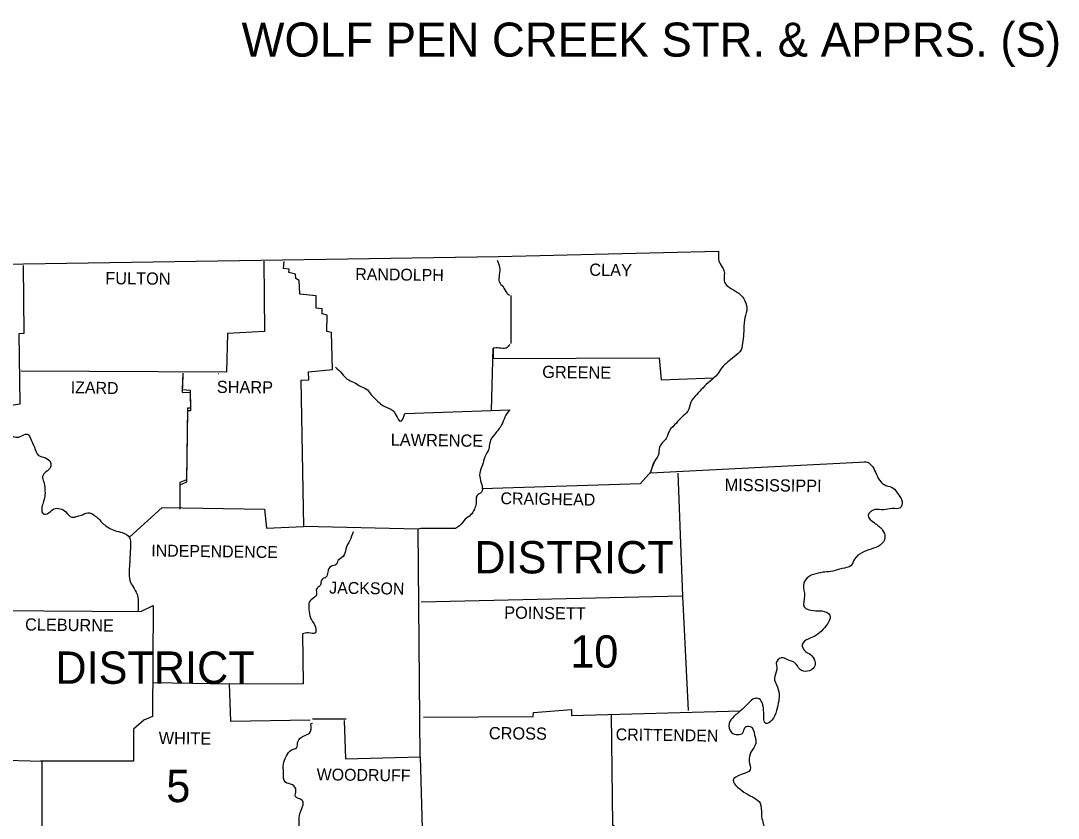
# Model space of a CAD drawing. Extents: x 1373884 to 1377798, y 1168424 to 1170626.
# Drawn here: x 1376598.2 to 1376963.9, y 1170086.2 to 1170367.2 of the extents above; entities that cross this region are included whole.
import ezdxf

# ---------------------------------------------------------------- set-up
doc = ezdxf.new("R2010")
doc.units = 0
doc.layers.add('1', color=7, linetype='Continuous')
doc.layers.add('R_Draft', color=7, linetype='Continuous')

msp = doc.modelspace()

# ---------------------------------------------------------------- linework, layer by layer
at = {"layer": 'R_Draft'}
for p, q in [((1376770.39, 1170230), (1376770.69, 1170230.1)), ((1376820.19, 1170207.9), (1376821.39, 1170211.6)), ((1376820.49, 1170209.1), (1376821.69, 1170212)), ((1376700.99, 1170121.3), (1376712.89, 1170121.3))]:
    msp.add_line(p, q, dxfattribs=at)
for points in [[(1376295.59, 1170281.4), (1376457.29, 1170281.3), (1376599.19, 1170281.6), (1376766.59, 1170284.2), (1376844.19, 1170286)], [(1376683.89, 1170282.5), (1376684.09, 1170257.7), (1376671.09, 1170257), (1376670.69, 1170243.4), (1376598.39, 1170243.8)], [(1376712.19, 1170120.7), (1376712.69, 1170107.2), (1376738.99, 1170107.9), (1376738.29, 1170188.1), (1376697.99, 1170189), (1376697.09, 1170240.6), (1376699.69, 1170240.7), (1376699.59, 1170243.5), (1376708.09, 1170244.3), (1376707.69, 1170257.4), (1376706.09, 1170257.7), (1376706.19, 1170263.5), (1376704.39, 1170264), (1376704.39, 1170265.7), (1376702.29, 1170266), (1376702.29, 1170270.3), (1376696.59, 1170270.9), (1376696.29, 1170275.7), (1376695.19, 1170276.4), (1376694.99, 1170278), (1376692.69, 1170278.5), (1376692.79, 1170279.7), (1376690.79, 1170280), (1376691.09, 1170282.4)], [(1376568.89, 1170039.7), (1376591.39, 1170039.8), (1376592.39, 1170051.6), (1376605.79, 1170052.6), (1376605.79, 1170106.2), (1376588.79, 1170106.7), (1376589.09, 1170159.4), (1376567.69, 1170160.8), (1376567.39, 1170184.4), (1376566.69, 1170185.6), (1376567.29, 1170200.4), (1376579.69, 1170200.8), (1376580.19, 1170213), (1376593.79, 1170213.5), (1376593.99, 1170221.4), (1376591.59, 1170224.5), (1376590.99, 1170231.2), (1376597.99, 1170232.2), (1376597.69, 1170257.1), (1376599.39, 1170257.2), (1376599.19, 1170281)], [(1376770.99, 1170270.4), (1376770.99, 1170253.5)], [(1376764.17, 1170229.87), (1376764.69, 1170251.9), (1376764.69, 1170248.2), (1376823.19, 1170248.5), (1376823.99, 1170240.7), (1376842.35, 1170241.37)], [(1376655.29, 1170243.1), (1376655.09, 1170237.3), (1376657.89, 1170237.1), (1376657.99, 1170230.7), (1376656.99, 1170230.7), (1376656.59, 1170205.5), (1376654.29, 1170204.5), (1376654.29, 1170196.1)], [(1376655.29, 1170242.2), (1376655.09, 1170236.4), (1376657.89, 1170236.2), (1376657.99, 1170229.8), (1376656.99, 1170229.8), (1376656.59, 1170204.6), (1376654.29, 1170203.6), (1376654.29, 1170195.2)], [(1376667.79, 1170242.9), (1376667.89, 1170243)], [(1376733.59, 1170228.8), (1376770.69, 1170230.1)], [(1376820.19, 1170207.9), (1376896.09, 1170211.8)], [(1376760.69, 1170202.39), (1376816.69, 1170204.2), (1376820.36, 1170208.43)], [(1376829.79, 1170207.8), (1376831.49, 1170164.5), (1376833.49, 1170124.2)], [(1376636.69, 1170185.4), (1376648.09, 1170195.7), (1376684.09, 1170195.2), (1376684.79, 1170188.5), (1376697.89, 1170189)], [(1376751.39, 1170188.3), (1376739.19, 1170188.3), (1376738.29, 1170188.1)], [(1376831.49, 1170164.5), (1376739.39, 1170162.4)], [(1376589.09, 1170159.4), (1376640.49, 1170159.1), (1376644.89, 1170161.2), (1376644.59, 1170122.1), (1376641.59, 1170120.8), (1376638.89, 1170118.5), (1376637.99, 1170117.6), (1376637.89, 1170106.4), (1376605.19, 1170106.4)], [(1376697.49, 1170151.2), (1376697.69, 1170133.6), (1376671.69, 1170133.5), (1376644.99, 1170134)], [(1376671.69, 1170133.5), (1376672.09, 1170120.4), (1376700.19, 1170120.9)], [(1376740.19, 1170121.9), (1376778.79, 1170122.1), (1376778.89, 1170123.5), (1376792.29, 1170124.5), (1376792.29, 1170122.4), (1376851.86, 1170124.04)], [(1376806.29, 1170122.79), (1376806.79, 1170083.9), (1376807.69, 1170083.3), (1376808.01, 1170077.77)], [(1376700.99, 1170119.6), (1376700.49, 1170119.5)], [(1376738.99, 1170107.9), (1376740.49, 1170053.1), (1376716.69, 1170053), (1376716.59, 1170050.8), (1376709.69, 1170050.4), (1376709.09, 1170039), (1376700.69, 1170039)]]:
    msp.add_lwpolyline(points, dxfattribs=at)
for points in [[(1376844.19, 1170286), (1376844.69, 1170281.6), (1376846.09, 1170279.3), (1376846.29, 1170275.1), (1376847.99, 1170273.3), (1376850.89, 1170271.5), (1376853.49, 1170268.6), (1376854.09, 1170265.2), (1376853.29, 1170261.7), (1376853.09, 1170257.8), (1376852.69, 1170254.4), (1376852.09, 1170251.3), (1376849.69, 1170248.8), (1376847.39, 1170247), (1376845.29, 1170244.9), (1376843.79, 1170242.7), (1376841.19, 1170240.3), (1376838.59, 1170237.8), (1376836.49, 1170235.6), (1376834.39, 1170232.8), (1376833.39, 1170229.7), (1376831.09, 1170227.5), (1376829.29, 1170225.5), (1376826.89, 1170222.8), (1376825.69, 1170220.1), (1376823.39, 1170217), (1376822.89, 1170214), (1376821.39, 1170211.6), (1376821.29, 1170211.2)], [(1376844.19, 1170286), (1376844.69, 1170281.6), (1376846.09, 1170279.3), (1376846.29, 1170275.1), (1376847.99, 1170273.3), (1376850.89, 1170271.5), (1376853.49, 1170268.6), (1376854.09, 1170265.2), (1376853.29, 1170261.7), (1376853.09, 1170257.8), (1376852.69, 1170254.4), (1376852.09, 1170251.3), (1376849.69, 1170248.8), (1376847.39, 1170247), (1376845.29, 1170244.9), (1376843.79, 1170242.7), (1376841.19, 1170240.3), (1376838.59, 1170237.8), (1376836.49, 1170235.6), (1376834.39, 1170232.8), (1376833.39, 1170229.7), (1376831.09, 1170227.5), (1376829.29, 1170225.5), (1376826.89, 1170222.8), (1376825.69, 1170220.1), (1376823.39, 1170217), (1376822.89, 1170214), (1376821.39, 1170211.6), (1376821.29, 1170211.2)], [(1376766.09, 1170282.9), (1376766.99, 1170280.4), (1376766.89, 1170277.7), (1376766.89, 1170275.2), (1376768.19, 1170273.5), (1376769.49, 1170271.4), (1376770.49, 1170270.5)], [(1376770.59, 1170253.2), (1376769.29, 1170251.9), (1376766.79, 1170251.9), (1376764.69, 1170251.9)], [(1376709.19, 1170245.2), (1376711.39, 1170242.9), (1376713.29, 1170241), (1376715.49, 1170239.9), (1376718.09, 1170238.4), (1376720.39, 1170237.2), (1376721.89, 1170235.3), (1376723.99, 1170233.2), (1376726.09, 1170231.5), (1376729.39, 1170229.9), (1376730.49, 1170228.2), (1376731.99, 1170226.1), (1376733.59, 1170228.8)], [(1376770.39, 1170230), (1376768.89, 1170227.6), (1376767.69, 1170224.8), (1376765.29, 1170221.6), (1376763.49, 1170218.5), (1376763.19, 1170216.4), (1376761.79, 1170213.6), (1376760.99, 1170210.8), (1376760.09, 1170208.4), (1376760.09, 1170205.9), (1376760.79, 1170203.4), (1376760.59, 1170201.1), (1376759.09, 1170200), (1376758.69, 1170197.1), (1376758.09, 1170195.1), (1376756.79, 1170193.1), (1376754.89, 1170191.6), (1376752.89, 1170189.3), (1376751.39, 1170188.3)], [(1376593.99, 1170221.4), (1376597.99, 1170220.7), (1376600.39, 1170221.6), (1376602.09, 1170219), (1376602.99, 1170217), (1376604.49, 1170214.1), (1376606.89, 1170213.2), (1376608.69, 1170211.6), (1376608.69, 1170209.9), (1376607.09, 1170208.3), (1376605.89, 1170206.7), (1376606.29, 1170204.8), (1376606.69, 1170202.2), (1376606.69, 1170199.7), (1376606.09, 1170197.4), (1376605.59, 1170195.3), (1376606.09, 1170193.5), (1376607.99, 1170193.8), (1376609.99, 1170195.3), (1376612.09, 1170195.3), (1376614.09, 1170194.2), (1376616.19, 1170192.3), (1376618.29, 1170192.7), (1376619.99, 1170193.2), (1376622.39, 1170193.9), (1376624.09, 1170193), (1376625.59, 1170191.8), (1376627.39, 1170189.9), (1376629.09, 1170188.7), (1376631.29, 1170187.6), (1376633.99, 1170186.9), (1376636.49, 1170185.2), (1376636.89, 1170182.3), (1376636.79, 1170179.8), (1376636.59, 1170176.7), (1376636.39, 1170173.3), (1376636.69, 1170170), (1376637.79, 1170167.8), (1376639.19, 1170165.2), (1376639.59, 1170162.8), (1376639.49, 1170159)], [(1376894.99, 1170211.7), (1376896.09, 1170211.8), (1376899.49, 1170208.2), (1376900.99, 1170205.2), (1376903.19, 1170203.5), (1376905.69, 1170202.6), (1376907.59, 1170200.3), (1376908.89, 1170197.8), (1376908.19, 1170195.6), (1376905.39, 1170195.4), (1376902.29, 1170194.9), (1376899.29, 1170195), (1376896.89, 1170193), (1376899.09, 1170190.3), (1376901.99, 1170187.8), (1376902.79, 1170185.1), (1376901.19, 1170182.5), (1376897.99, 1170181.1), (1376894.89, 1170179.9), (1376892.09, 1170177.5), (1376890.79, 1170175.2), (1376887.69, 1170174.2), (1376884.49, 1170173.3), (1376881.69, 1170173), (1376878.49, 1170172.4), (1376875.39, 1170170.9), (1376874.09, 1170168.3), (1376874.49, 1170164.6), (1376874.39, 1170160.7), (1376877.69, 1170159.4), (1376880.59, 1170159.3), (1376883.39, 1170157.8), (1376883.09, 1170155.6), (1376880.99, 1170152.8), (1376878.49, 1170150.6), (1376875.99, 1170149.5), (1376873.69, 1170147.4), (1376874.49, 1170145.3), (1376876.59, 1170143.9), (1376878.09, 1170141.6), (1376877.89, 1170139.5), (1376875.49, 1170138), (1376872.89, 1170138.6), (1376870.99, 1170141.1), (1376868.79, 1170141.9), (1376866.89, 1170142.8), (1376864.69, 1170141.5), (1376864.69, 1170138.6), (1376863.89, 1170135.5), (1376864.59, 1170133.2), (1376865.49, 1170130), (1376865.39, 1170127.6), (1376864.59, 1170124.2), (1376862.89, 1170120.7), (1376860.89, 1170119.6), (1376860.09, 1170123.4), (1376859.69, 1170126.5), (1376858.49, 1170128.3), (1376856.89, 1170128.4), (1376854.79, 1170126.9), (1376852.49, 1170124.6), (1376849.59, 1170122.1), (1376847.89, 1170119.6), (1376848.79, 1170116.5), (1376850.99, 1170115.7), (1376852.69, 1170116.3), (1376853.59, 1170118.3), (1376855.29, 1170118.6), (1376856.89, 1170115.5)], [(1376894.99, 1170211.7), (1376896.09, 1170211.8), (1376899.49, 1170208.2), (1376900.99, 1170205.2), (1376903.19, 1170203.5), (1376905.69, 1170202.6), (1376907.59, 1170200.3), (1376908.89, 1170197.8), (1376908.19, 1170195.6), (1376905.39, 1170195.4), (1376902.29, 1170194.9), (1376899.29, 1170195), (1376896.89, 1170193), (1376899.09, 1170190.3), (1376901.99, 1170187.8), (1376902.79, 1170185.1), (1376901.19, 1170182.5), (1376897.99, 1170181.1), (1376894.89, 1170179.9), (1376892.09, 1170177.5), (1376890.79, 1170175.2), (1376887.69, 1170174.2), (1376884.49, 1170173.3), (1376881.69, 1170173), (1376878.49, 1170172.4), (1376875.39, 1170170.9), (1376874.09, 1170168.3), (1376874.49, 1170164.6), (1376874.39, 1170160.7), (1376877.69, 1170159.4), (1376880.59, 1170159.3), (1376883.39, 1170157.8), (1376883.09, 1170155.6), (1376880.99, 1170152.8), (1376878.49, 1170150.6), (1376875.99, 1170149.5), (1376873.69, 1170147.4), (1376874.49, 1170145.3), (1376876.59, 1170143.9), (1376878.09, 1170141.6), (1376877.89, 1170139.5), (1376875.49, 1170138), (1376872.89, 1170138.6), (1376870.99, 1170141.1), (1376868.79, 1170141.9), (1376866.89, 1170142.8), (1376864.69, 1170141.5), (1376864.69, 1170138.6), (1376863.89, 1170135.5), (1376864.59, 1170133.2), (1376865.49, 1170130), (1376865.39, 1170127.6), (1376864.59, 1170124.2), (1376862.89, 1170120.7), (1376860.89, 1170119.6), (1376860.09, 1170123.4), (1376859.69, 1170126.5), (1376858.49, 1170128.3), (1376856.89, 1170128.4), (1376854.79, 1170126.9), (1376852.49, 1170124.6), (1376849.59, 1170122.1), (1376847.89, 1170119.6), (1376848.79, 1170116.5), (1376850.99, 1170115.7), (1376852.69, 1170116.3), (1376853.59, 1170118.3), (1376855.29, 1170118.6), (1376856.89, 1170115.5)], [(1376715.39, 1170187.2), (1376714.19, 1170184.1), (1376712.79, 1170181.1), (1376711.89, 1170178.5), (1376709.99, 1170177), (1376709.39, 1170175.6), (1376707.69, 1170175), (1376706.39, 1170173), (1376705.79, 1170171.2), (1376704.39, 1170170.4), (1376703.69, 1170168.2), (1376702.39, 1170167), (1376702.49, 1170165), (1376700.99, 1170163.6), (1376699.79, 1170162), (1376699.79, 1170159.8), (1376700.29, 1170156.9), (1376701.29, 1170155.2), (1376702.19, 1170153), (1376702.09, 1170151.6), (1376699.59, 1170151.6), (1376697.49, 1170151.2)], [(1376688.29, 1170059.8), (1376687.79, 1170060.5), (1376688.39, 1170062.7), (1376688.69, 1170064.1), (1376687.69, 1170066.1), (1376688.59, 1170067.8), (1376689.59, 1170069.6), (1376689.89, 1170071.7), (1376690.69, 1170073.1), (1376690.39, 1170074.9), (1376690.79, 1170077.4), (1376691.89, 1170079.3), (1376693.49, 1170082), (1376696.19, 1170082.7), (1376696.39, 1170083.8), (1376696.29, 1170086.3), (1376697.39, 1170090), (1376697.79, 1170091.3), (1376697.39, 1170092.5), (1376694.99, 1170093.9), (1376695.19, 1170096), (1376693.99, 1170098), (1376691.49, 1170098.9), (1376690.79, 1170102.3), (1376690.79, 1170105.3), (1376691.89, 1170108.2), (1376693.59, 1170110.3), (1376695.39, 1170111.1), (1376695.89, 1170113.1), (1376698.09, 1170115.3), (1376699.99, 1170116.2), (1376700.49, 1170119.5)], [(1376856.89, 1170115.5), (1376857.29, 1170112.6), (1376855.59, 1170109.5), (1376854.99, 1170106.4), (1376855.29, 1170103.3), (1376852.09, 1170101.6), (1376849.29, 1170099.6), (1376850.89, 1170097.2), (1376853.89, 1170095), (1376856.89, 1170093.3), (1376858.79, 1170091.6), (1376859.29, 1170087.5), (1376859.79, 1170084.9), (1376860.79, 1170081.3), (1376861.19, 1170078.8), (1376859.39, 1170075.8), (1376857.29, 1170075.2), (1376855.09, 1170075.9), (1376852.49, 1170076.1), (1376850.39, 1170074.1), (1376848.89, 1170071.3), (1376847.39, 1170068.5), (1376846.29, 1170066.1), (1376845.19, 1170063.5), (1376842.99, 1170060.5), (1376840.29, 1170060), (1376837.09, 1170059.2), (1376835.19, 1170057), (1376835.49, 1170053.3), (1376837.29, 1170050.8), (1376838.69, 1170047.7), (1376839.69, 1170045), (1376839.19, 1170041.6), (1376837.79, 1170039.1), (1376835.99, 1170037.6), (1376835.19, 1170034.4), (1376833.89, 1170032), (1376832.69, 1170031.2), (1376830.29, 1170031.4), (1376827.69, 1170031.9), (1376825.49, 1170031.7), (1376823.39, 1170030.6), (1376821.29, 1170031.3), (1376819.09, 1170033.7), (1376817.29, 1170035.5), (1376815.29, 1170036.2), (1376813.19, 1170035.1), (1376812.79, 1170031.8), (1376813.79, 1170028.4), (1376814.69, 1170023.8), (1376813.79, 1170021), (1376813.49, 1170016.4)], [(1376856.89, 1170115.5), (1376857.29, 1170112.6), (1376855.59, 1170109.5), (1376854.99, 1170106.4), (1376855.29, 1170103.3), (1376852.09, 1170101.6), (1376849.29, 1170099.6), (1376850.89, 1170097.2), (1376853.89, 1170095), (1376856.89, 1170093.3), (1376858.79, 1170091.6), (1376859.29, 1170087.5), (1376859.79, 1170084.9), (1376860.79, 1170081.3), (1376861.19, 1170078.8), (1376859.39, 1170075.8), (1376857.29, 1170075.2), (1376855.09, 1170075.9), (1376852.49, 1170076.1), (1376850.39, 1170074.1), (1376848.89, 1170071.3), (1376847.39, 1170068.5), (1376846.29, 1170066.1), (1376845.19, 1170063.5), (1376842.99, 1170060.5), (1376840.29, 1170060), (1376837.09, 1170059.2), (1376835.19, 1170057), (1376835.49, 1170053.3), (1376837.29, 1170050.8), (1376838.69, 1170047.7), (1376839.69, 1170045), (1376839.19, 1170041.6), (1376837.79, 1170039.1), (1376835.99, 1170037.6), (1376835.19, 1170034.4), (1376833.89, 1170032), (1376832.69, 1170031.2), (1376830.29, 1170031.4), (1376827.69, 1170031.9), (1376825.49, 1170031.7), (1376823.39, 1170030.6), (1376821.29, 1170031.3), (1376819.09, 1170033.7), (1376817.29, 1170035.5), (1376815.29, 1170036.2), (1376813.19, 1170035.1), (1376812.79, 1170031.8), (1376813.79, 1170028.4), (1376814.69, 1170023.8), (1376813.79, 1170021), (1376813.49, 1170016.4)]]:
    msp.add_spline(points, degree=3, dxfattribs=at)

# ---------------------------------------------------------------- texts
at = {"layer": '1'}
msp.add_text('WOLF PEN CREEK STR. & APPRS. (S)', height=12, dxfattribs=at).set_placement((1376676.02, 1170354.6))
at = {"layer": 'R_Draft'}
for s, height, rotation, p in [('CLAY', 4.3, 359.2258, (1376798.59, 1170277.4)), ('FULTON', 4.3, 359.4996, (1376627.99, 1170274.4)), ('RANDOLPH', 4.201, 359.2583, (1376716.09, 1170275.9)), ('GREENE', 4.301, 359.2361, (1376781.99, 1170241.4)), ('IZARD', 4.199, 358.9258, (1376615.79, 1170236)), ('SHARP', 4.3, 359.3905, (1376667.29, 1170236.1)), ('LAWRENCE', 4.301, 359.2678, (1376728.59, 1170217.5)), ('MISSISSIPPI', 4.2996, 359.3097, (1376846.29, 1170201.6)), ('CRAIGHEAD', 4.201, 359.1159, (1376767.29, 1170196.9)), ('INDEPENDENCE', 4.1994, 359.2187, (1376644.19, 1170178.5)), ('JACKSON', 4.199, 359.1352, (1376706.89, 1170165.4)), ('POINSETT', 4.3, 359.1987, (1376768.59, 1170156.6)), ('CLEBURNE', 4.3, 359.2535, (1376599.69, 1170152.4)), ('WHITE', 4.301, 359.3139, (1376646.79, 1170112.4)), ('CROSS', 4.3, 359.3839, (1376763.19, 1170114.1)), ('CRITTENDEN', 4.201, 359.213, (1376807.89, 1170113.7)), ('WOODRUFF', 4.199, 359.2748, (1376702.49, 1170099.6))]:
    msp.add_text(s, height=height, rotation=rotation, dxfattribs=at).set_placement(p)
for s, p in [('DISTRICT', (1376758.09, 1170172.5)), ('10', (1376791.89, 1170139.3)), ('DISTRICT', (1376610.39, 1170133.6)), ('5', (1376649.49, 1170091.9))]:
    msp.add_text(s, height=11.4, dxfattribs=at).set_placement(p)

doc.saveas('drawing.dxf')
